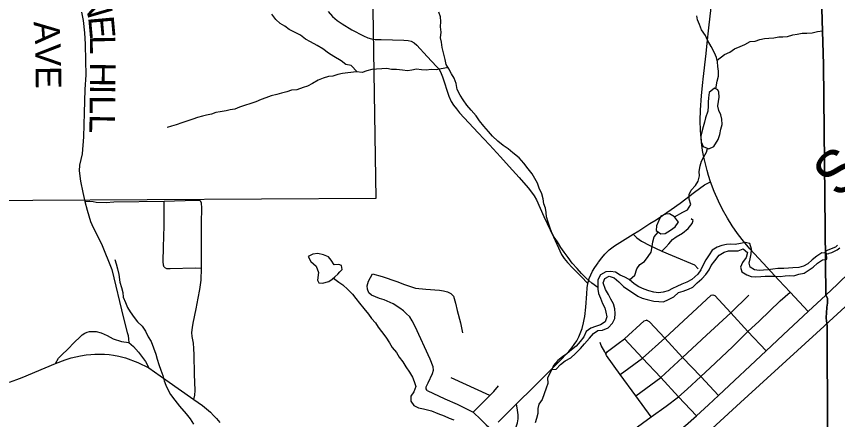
# Model space of a CAD drawing. Extents: x 0 to 34, y 0 to 22.
# Drawn here: x 4.481 to 6.308, y 17.511 to 18.409 of the extents above; entities that cross this region are included whole.
import ezdxf

# ---------------------------------------------------------------- set-up
doc = ezdxf.new("R2010")
doc.units = 0
doc.layers.add('Default', color=7, linetype='Continuous')
doc.layers.add('SH_Cut_Line', color=7, linetype='Continuous')

msp = doc.modelspace()

# ---------------------------------------------------------------- linework, layer by layer
at = {"layer": 'Default'}
for p, q in [((6.281, 17.8795), (6.2884, 17.8811)), ((5.3686, 17.8044), (5.3919, 17.8021)), ((6.2422, 17.7524), (6.282, 17.7887)), ((6.1986, 17.7113), (6.2422, 17.7524)), ((6.1986, 17.7113), (6.2422, 17.7524)), ((5.5344, 17.5651), (5.4477, 17.6045))]:
    msp.add_line(p, q, dxfattribs=at)
for points in [[(8.9, 20.9), (6.2315, 20.9), (6.2432, 19.8937), (6.2705, 18.5012), (6.2766, 18.3021), (6.2818, 17.7893), (6.284, 17.7847), (6.2852, 17.7812), (6.2857, 17.7766), (6.2851, 17.77), (6.2847, 17.7673), (6.2837, 17.7609), (6.2829, 17.749), (6.2828, 17.7387), (6.2833, 17.73), (6.2837, 17.7277), (6.2841, 17.7253), (6.2843, 17.721), (6.2843, 17.7119), (6.2861, 17.2714), (6.2871, 17.0188), (6.3215, 17.0189)], [(6.0178, 18.3496), (6.0215, 18.3835), (6.0286, 18.4495), (6.0333, 18.4968), (6.0336, 18.4999)], [(6.2861, 17.2714), (6.2843, 17.7119), (6.2843, 17.721), (6.2841, 17.7253), (6.2837, 17.7277), (6.2833, 17.73), (6.2828, 17.7387), (6.2829, 17.749), (6.2837, 17.7609), (6.2847, 17.7673), (6.2851, 17.77), (6.2857, 17.7766), (6.2852, 17.7812), (6.284, 17.7847), (6.2818, 17.7893), (6.2766, 18.3021), (6.2705, 18.5012)], [(4.6255, 18.4186), (4.6295, 18.3999), (4.6323, 18.3725), (4.6339, 18.3476), (4.6346, 18.3103), (4.6348, 18.2791), (4.6327, 18.2467), (4.631, 18.1946), (4.6296, 18.1414), (4.6272, 18.103), (4.6209, 18.0778), (4.6204, 18.0653), (4.6229, 18.0422), (4.6285, 18.0168), (4.6331, 17.9968), (4.6379, 17.9777), (4.6455, 17.9529), (4.6513, 17.9393), (4.6697, 17.903), (4.6929, 17.8458), (4.719, 17.7371), (4.7271, 17.7056), (4.7289, 17.6983), (4.7299, 17.6905), (4.7309, 17.6828)], [(5.1741, 18.42), (5.184, 18.4092), (5.1943, 18.4002), (5.2052, 18.3924), (5.227, 18.3797), (5.2531, 18.3657), (5.2625, 18.3614), (5.2706, 18.3591), (5.2792, 18.3578), (5.2906, 18.3575), (5.2926, 18.3575)], [(5.7742, 17.8052), (5.761, 17.815), (5.7487, 17.8266), (5.738, 17.8368), (5.728, 17.8477), (5.7172, 17.8598), (5.7083, 17.8726), (5.6998, 17.8839), (5.6917, 17.8949), (5.6843, 17.9073), (5.6774, 17.9179), (5.6712, 17.9296), (5.6673, 17.9398), (5.6641, 17.9508), (5.6605, 17.963), (5.6597, 17.9725), (5.6577, 17.9819), (5.6545, 17.9918), (5.6529, 18.0028), (5.6497, 18.0141), (5.6439, 18.027), (5.6403, 18.038), (5.6341, 18.0486), (5.6283, 18.0588), (5.6191, 18.0701), (5.6094, 18.0822), (5.5994, 18.0942), (5.5852, 18.1055), (5.5745, 18.1145), (5.5634, 18.1216), (5.5515, 18.1314), (5.5403, 18.1427), (5.5307, 18.1528), (5.5207, 18.1649), (5.5111, 18.177), (5.5033, 18.1875), (5.4925, 18.2007), (5.4825, 18.2117), (5.4748, 18.2234), (5.4682, 18.2339), (5.4612, 18.2468), (5.4592, 18.2597), (5.4545, 18.2714), (5.4487, 18.2816), (5.4429, 18.2926), (5.4371, 18.3024), (5.4347, 18.313), (5.4311, 18.3282), (5.4279, 18.3399), (5.4262, 18.3521), (5.4246, 18.3616), (5.4256, 18.3745), (5.424, 18.3859), (5.425, 18.3977), (5.4245, 18.4083), (5.4202, 18.4185)], [(5.2389, 18.2859), (5.2254, 18.2997), (5.2139, 18.3022), (5.2032, 18.3101), (5.1867, 18.3202), (5.1749, 18.3273), (5.1622, 18.3371), (5.15, 18.3446), (5.1351, 18.3528), (5.124, 18.3587), (5.1125, 18.3678), (5.0991, 18.3745), (5.0876, 18.3804), (5.0781, 18.3872), (5.0673, 18.3935), (5.0577, 18.4022), (5.0489, 18.4143)], [(6.0367, 18.2479), (6.0399, 18.2647), (6.0425, 18.2765), (6.0427, 18.2872), (6.0415, 18.2978), (6.041, 18.308), (6.0382, 18.3179), (6.0339, 18.3285), (6.0269, 18.3425), (6.0184, 18.3561), (6.0137, 18.3671), (6.0052, 18.3795), (6.0005, 18.3909), (5.9962, 18.4015), (5.9946, 18.4109)], [(6.04, 18.3117), (6.056, 18.3245), (6.0681, 18.33), (6.0787, 18.3369), (6.0908, 18.3419), (6.1017, 18.347), (6.1131, 18.3532), (6.1245, 18.3544), (6.1351, 18.3579), (6.1453, 18.3599), (6.1552, 18.3608), (6.1658, 18.3616), (6.1768, 18.3636), (6.1863, 18.3637), (6.1966, 18.3646), (6.2083, 18.3681), (6.2182, 18.3697), (6.2292, 18.3717), (6.2391, 18.3722), (6.2516, 18.3727), (6.263, 18.3758), (6.274, 18.3775)], [(5.2926, 18.3575), (5.343, 18.3565), (5.3521, 18.3558), (5.3592, 18.3539), (5.3657, 18.3503), (5.3716, 18.3454), (5.3949, 18.3203), (5.4155, 18.298), (5.4202, 18.2924), (5.4232, 18.2874), (5.4258, 18.2825), (5.4288, 18.2746), (5.4431, 18.2315), (5.4482, 18.2199), (5.453, 18.2118), (5.4596, 18.2033), (5.4669, 18.1943), (5.508, 18.15), (5.5334, 18.1229), (5.5581, 18.0964), (5.5772, 18.0751), (5.5991, 18.0508), (5.6191, 18.0276), (5.6271, 18.0178), (5.6328, 18.0097), (5.6379, 18.0007), (5.6543, 17.9639), (5.6755, 17.9185), (5.6829, 17.9024), (5.6938, 17.8794), (5.6997, 17.87), (5.7068, 17.8612), (5.7181, 17.8493), (5.7372, 17.8302), (5.7522, 17.8142)], [(6.009, 18.2698), (6.0153, 18.3268), (6.0178, 18.3496)], [(5.441, 18.2957), (5.4148, 18.2904), (5.4034, 18.2911), (5.392, 18.2898), (5.3817, 18.2905), (5.3707, 18.2919), (5.3604, 18.2892), (5.3509, 18.2883), (5.3395, 18.2897), (5.3262, 18.2907), (5.3152, 18.2914), (5.3049, 18.2932), (5.2939, 18.2923), (5.2817, 18.2915), (5.2715, 18.291), (5.2605, 18.2878), (5.2502, 18.2843), (5.2377, 18.2861), (5.2183, 18.2833), (5.2062, 18.2824), (5.1956, 18.2796), (5.1846, 18.2765), (5.1747, 18.2756), (5.163, 18.2714), (5.152, 18.2675), (5.1391, 18.2597), (5.1282, 18.2536), (5.1183, 18.2508), (5.1043, 18.2461), (5.0929, 18.2452), (5.082, 18.2413), (5.0702, 18.2386), (5.0604, 18.2351), (5.0475, 18.2327), (5.0354, 18.228), (5.0251, 18.2241), (5.0134, 18.2194), (5.0024, 18.2155), (4.988, 18.2108), (4.9767, 18.2069), (4.9668, 18.203), (4.9566, 18.201), (4.9471, 18.1991), (4.9342, 18.197), (4.9243, 18.195), (4.9145, 18.1919), (4.9039, 18.1892), (4.8944, 18.1872), (4.8834, 18.184), (4.8728, 18.1805), (4.8486, 18.1719), (4.8361, 18.1676), (4.8259, 18.1645), (4.8164, 18.1621), (4.816, 18.1617)], [(6.2422, 17.7524), (6.2023, 17.7949), (6.1769, 17.8221), (6.1419, 17.8597), (6.1126, 17.8917), (6.0983, 17.909), (6.0876, 17.9225), (6.0799, 17.9332), (6.0733, 17.9432), (6.0626, 17.9601), (6.0521, 17.9791), (6.0426, 17.9979), (6.0334, 18.0195), (6.0254, 18.0411), (6.0207, 18.0547), (6.0175, 18.0658), (6.0136, 18.0808), (6.0104, 18.0956), (6.0076, 18.111), (6.0051, 18.1294), (6.0028, 18.1549), (6.0019, 18.1773), (6.0026, 18.2007), (6.005, 18.233), (6.0081, 18.2618), (6.009, 18.2698)], [(6.0337, 18.2491), (6.0224, 18.2395), (6.0206, 18.2281), (6.0199, 18.2186), (6.0197, 18.2091), (6.0194, 18.1981), (6.0139, 18.1836), (6.0117, 18.174), (6.0088, 18.163), (6.0055, 18.1523), (6.0033, 18.1424), (6.0042, 18.1299), (6.0089, 18.1193), (6.0211, 18.1141), (6.0328, 18.1195), (6.0418, 18.1352), (6.0458, 18.1466), (6.048, 18.1581), (6.0509, 18.1683), (6.0504, 18.1801), (6.0484, 18.19), (6.0437, 18.1998), (6.0413, 18.2093), (6.0413, 18.21)], [(6.0413, 18.21), (6.0442, 18.2296), (6.0438, 18.2403), (6.0413, 18.2461), (6.0337, 18.2491)], [(6.282, 17.7887), (6.3073, 17.813), (6.3362, 17.8402), (6.3575, 17.8601), (6.3773, 17.8781), (6.3931, 17.8911), (6.4187, 17.9087), (6.4651, 17.9375), (6.491, 17.9548), (6.5185, 17.9718), (6.5797, 18.0093), (6.6681, 18.065), (6.6821, 18.0745), (6.7065, 18.0896), (6.7702, 18.1304)], [(5.9449, 17.963), (5.9637, 17.9734), (5.9736, 17.9788), (5.9814, 17.9903), (5.9775, 18.002), (5.9778, 18.0123), (5.9822, 18.0222), (5.9916, 18.0329), (5.9976, 18.0425), (6.0005, 18.0543), (6, 18.0641), (6.0018, 18.0763), (6.0054, 18.0866), (6.0103, 18.0969), (6.0159, 18.1072), (6.0183, 18.1153)], [(5.7762, 17.8619), (5.7832, 17.8714), (5.79, 17.8796), (5.7948, 17.8848), (5.7998, 17.8894), (5.8114, 17.898), (5.8234, 17.9056), (5.8533, 17.9243), (5.8657, 17.9321), (5.8904, 17.9478), (5.904, 17.9564), (5.9181, 17.9657), (5.9372, 17.9789), (5.9576, 17.9937), (5.9896, 18.0176), (6.0117, 18.0345), (6.0254, 18.0411)], [(4.6331, 17.9968), (4.6437, 17.9977), (4.6515, 17.997), (4.6582, 17.9956), (4.6803, 17.9948), (4.6977, 17.996), (4.8097, 17.998), (4.8792, 18.0002), (4.8851, 17.9998), (4.8885, 17.9991)], [(4.8755, 17.5559), (4.8775, 17.566), (4.878, 17.5764), (4.8766, 17.6125), (4.8758, 17.6559), (4.8757, 17.6698), (4.8745, 17.6813), (4.8719, 17.6964), (4.8713, 17.7052), (4.8724, 17.7166), (4.8742, 17.7262), (4.8809, 17.7581), (4.885, 17.7818), (4.8886, 17.8012), (4.8917, 17.8219), (4.8928, 17.8487), (4.8927, 17.8814), (4.8924, 17.9485), (4.8933, 17.9832), (4.8924, 17.9934), (4.8909, 17.9968), (4.8885, 17.9991)], [(4.8093, 17.8511), (4.8077, 17.8553), (4.8073, 17.8631), (4.8081, 17.8956), (4.8094, 17.9432), (4.8094, 17.9794), (4.8097, 17.998)], [(5.9449, 17.963), (5.9341, 17.9697), (5.9246, 17.9688), (5.9144, 17.9642), (5.9104, 17.9547), (5.9048, 17.9432), (5.9041, 17.9322), (5.9149, 17.9247), (5.9244, 17.9259), (5.9357, 17.9336), (5.9466, 17.9409), (5.953, 17.9505), (5.9537, 17.9513)], [(5.9537, 17.9513), (5.9449, 17.963)], [(6.2778, 17.7191), (6.2804, 17.7215), (6.5458, 17.9651)], [(5.9168, 17.8865), (5.9255, 17.8957), (5.9327, 17.9025), (5.9405, 17.9126), (5.9483, 17.9184), (5.9631, 17.9265), (5.9755, 17.937), (5.9841, 17.9483), (5.9865, 17.9546), (5.982, 17.9584)], [(5.8445, 17.8224), (5.8566, 17.8333), (5.861, 17.8471), (5.8681, 17.857), (5.8779, 17.8636), (5.8865, 17.8743), (5.8933, 17.8846), (5.895, 17.8971), (5.8968, 17.907), (5.8997, 17.9181), (5.9087, 17.929)], [(5.8533, 17.9243), (5.8613, 17.9164), (5.8712, 17.9089), (5.8902, 17.8992), (5.9168, 17.8865), (5.9396, 17.8768), (5.9891, 17.8558), (5.9979, 17.847)], [(6.2835, 17.8822), (6.2726, 17.8828), (6.2617, 17.8751), (6.2515, 17.8674), (6.2417, 17.8586), (6.2319, 17.8532), (6.2217, 17.8504), (6.208, 17.8492), (6.1985, 17.8487), (6.1879, 17.8478), (6.175, 17.8477), (6.1636, 17.8465), (6.1537, 17.8449), (6.1427, 17.8444), (6.1332, 17.8435), (6.1233, 17.8446), (6.113, 17.8506), (6.111, 17.86), (6.1131, 17.8696), (6.1153, 17.8802), (6.1163, 17.8909), (6.1128, 17.9034), (6.1025, 17.9055), (6.0915, 17.9039), (6.0801, 17.9012), (6.0706, 17.9018), (6.0607, 17.901), (6.0505, 17.899), (6.0399, 17.8955), (6.0289, 17.8885), (6.0218, 17.8782), (6.0147, 17.8675), (6.0095, 17.8576), (6.0036, 17.845), (5.9968, 17.8354), (5.9833, 17.8235), (5.9723, 17.8173), (5.961, 17.813), (5.9504, 17.8076), (5.9406, 17.8034), (5.9307, 17.7983), (5.9197, 17.7952), (5.9091, 17.7936), (5.8988, 17.795), (5.8878, 17.7983), (5.8771, 17.802), (5.8653, 17.8068), (5.8553, 17.814), (5.8438, 17.823), (5.8342, 17.8286), (5.8243, 17.8327), (5.814, 17.8394), (5.8029, 17.8412), (5.7919, 17.8403), (5.7806, 17.8338), (5.7746, 17.8223), (5.7743, 17.8124), (5.7741, 17.8018), (5.7757, 17.7923), (5.7804, 17.7821), (5.7847, 17.77), (5.7898, 17.7602), (5.7921, 17.7503), (5.7942, 17.7401), (5.7909, 17.729), (5.7803, 17.7225), (5.7689, 17.7189), (5.7587, 17.715), (5.7481, 17.7077), (5.7433, 17.6955), (5.7347, 17.6856), (5.7265, 17.6748), (5.7159, 17.6664), (5.7057, 17.6576), (5.6956, 17.651), (5.685, 17.6429), (5.6756, 17.6322), (5.672, 17.6233)], [(5.672, 17.6233), (5.6814, 17.6239), (5.6916, 17.6339), (5.7017, 17.6419), (5.7142, 17.6489), (5.7244, 17.6589), (5.7356, 17.6696), (5.7446, 17.6803), (5.7559, 17.693), (5.7645, 17.7029), (5.7747, 17.7095), (5.785, 17.7107), (5.7975, 17.7154), (5.8072, 17.7258), (5.8121, 17.7364), (5.8127, 17.7478), (5.8122, 17.7581), (5.809, 17.7691), (5.8036, 17.7793), (5.7978, 17.7899), (5.7912, 17.8012), (5.7865, 17.8156), (5.7898, 17.8255), (5.7996, 17.8309), (5.8107, 17.8268), (5.821, 17.8182), (5.8314, 17.808), (5.841, 17.8013), (5.8517, 17.7942), (5.8632, 17.7859), (5.8731, 17.7818), (5.8842, 17.7789), (5.8987, 17.7752), (5.9101, 17.7746), (5.9207, 17.7735), (5.9313, 17.7786), (5.9434, 17.7848), (5.9536, 17.7947), (5.9646, 17.7975), (5.9763, 17.8022), (5.9861, 17.8061), (5.9955, 17.8156), (6.0061, 17.8245), (6.0147, 17.8344), (6.0218, 17.8451), (6.0263, 17.8547), (6.0349, 17.865), (6.0446, 17.8773), (6.0556, 17.8842), (6.0654, 17.8873), (6.0863, 17.8875), (6.0977, 17.8918), (6.1073, 17.8832), (6.1047, 17.8725), (6.0965, 17.8614), (6.0921, 17.8507), (6.0948, 17.8405), (6.1059, 17.8338), (6.1159, 17.8301), (6.1261, 17.829), (6.1371, 17.8299), (6.147, 17.8307), (6.1698, 17.831), (6.1801, 17.8303), (6.1911, 17.8312), (6.2006, 17.832), (6.2105, 17.8317), (6.2219, 17.8352), (6.2332, 17.8372), (6.2536, 17.8511), (6.2634, 17.8596), (6.274, 17.8669), (6.2837, 17.8689)], [(6.3078, 17.9001), (6.3029, 17.8956), (6.2976, 17.8933), (6.2923, 17.8906), (6.2863, 17.889), (6.2798, 17.8848), (6.281, 17.8795)], [(6.2884, 17.8811), (6.2883, 17.8813), (6.2893, 17.882), (6.295, 17.8834), (6.3008, 17.8864), (6.3071, 17.8891), (6.3125, 17.8941)], [(5.2053, 17.8459), (5.2041, 17.8546), (5.198, 17.8564), (5.1877, 17.856), (5.1812, 17.8665), (5.175, 17.8741), (5.1639, 17.8785), (5.1513, 17.8811), (5.14, 17.8798), (5.1301, 17.8744), (5.1356, 17.8631), (5.1475, 17.8533), (5.153, 17.8389), (5.1505, 17.8222), (5.1532, 17.8158), (5.162, 17.8151), (5.1756, 17.8186)], [(6.2837, 17.8689), (6.2835, 17.8822)], [(4.6999, 17.8681), (4.7023, 17.8579), (4.7055, 17.8473), (4.7083, 17.8344), (4.7104, 17.8173), (4.7147, 17.8056), (4.7171, 17.7942), (4.718, 17.7843), (4.7234, 17.7722), (4.7277, 17.7609), (4.7339, 17.7511), (4.7424, 17.739), (4.7501, 17.7292), (4.7605, 17.7194), (4.7675, 17.7084), (4.7737, 17.696), (4.7803, 17.685), (4.7857, 17.6714), (4.7908, 17.6574), (4.794, 17.646), (4.7976, 17.6343), (4.8019, 17.6214), (4.8062, 17.6093), (4.8097, 17.5979), (4.8129, 17.5877), (4.818, 17.5771), (4.8238, 17.5669), (4.833, 17.5548), (4.8438, 17.5412), (4.8585, 17.5239), (4.8669, 17.5133), (4.8747, 17.5009)], [(5.7441, 17.7344), (5.7452, 17.741), (5.7475, 17.762), (5.7497, 17.7918), (5.7508, 17.8047), (5.7522, 17.8142), (5.755, 17.8253), (5.7586, 17.8341), (5.7625, 17.8417), (5.768, 17.8503), (5.7752, 17.8605), (5.7762, 17.8619)], [(4.8093, 17.8511), (4.8147, 17.8481), (4.8229, 17.8475), (4.878, 17.8496), (4.8928, 17.8487)], [(5.1756, 17.8186), (5.1833, 17.824), (5.1893, 17.8292), (5.1955, 17.8349), (5.2, 17.8406), (5.2053, 17.8459)], [(5.3944, 17.5763), (5.3924, 17.5802), (5.3927, 17.5845), (5.3966, 17.5931), (5.4065, 17.6138), (5.4085, 17.6214), (5.4082, 17.6286), (5.4009, 17.6458), (5.368, 17.7189), (5.3611, 17.731), (5.3558, 17.7399), (5.3476, 17.7478), (5.342, 17.7534), (5.3338, 17.7597), (5.3193, 17.7692), (5.2992, 17.7781), (5.2888, 17.7811), (5.2707, 17.7886), (5.2649, 17.7939), (5.2618, 17.8017), (5.2613, 17.809), (5.2638, 17.8195), (5.2727, 17.8362), (5.2948, 17.8304), (5.327, 17.8188), (5.3438, 17.8125), (5.3686, 17.8044)], [(5.1862, 17.8264), (5.1977, 17.8177), (5.2072, 17.8113), (5.218, 17.8012), (5.2284, 17.791), (5.2361, 17.7808), (5.2442, 17.7706), (5.2538, 17.7586), (5.2638, 17.7465), (5.2708, 17.7367), (5.2793, 17.7269), (5.2854, 17.7171), (5.2932, 17.7073), (5.3024, 17.6948), (5.3109, 17.682), (5.3167, 17.6722), (5.326, 17.6609), (5.3326, 17.6507), (5.3407, 17.6401), (5.3469, 17.6291), (5.355, 17.6171), (5.3623, 17.6061), (5.3659, 17.5963), (5.3694, 17.5853), (5.3646, 17.5735), (5.3586, 17.5639), (5.3584, 17.5525), (5.3649, 17.5427), (5.3753, 17.5375), (5.3867, 17.5357), (5.4046, 17.5309), (5.418, 17.5253), (5.4321, 17.5198), (5.4432, 17.5142), (5.4539, 17.5108)], [(5.3919, 17.8021), (5.422, 17.7993), (5.4307, 17.798), (5.4402, 17.7961), (5.4472, 17.7925), (5.4529, 17.7863), (5.4573, 17.7708), (5.4611, 17.7546), (5.4684, 17.7266), (5.473, 17.7049)], [(5.7174, 17.3816), (5.7506, 17.4092), (5.791, 17.4423), (5.8355, 17.4754), (5.8932, 17.5172), (5.9264, 17.5412), (5.9539, 17.5623), (5.9734, 17.579), (6.0034, 17.6071), (6.0243, 17.627), (6.0741, 17.6736), (6.1079, 17.7075), (6.1331, 17.7308), (6.1804, 17.7762), (6.2023, 17.7949)], [(5.8241, 17.6118), (5.8738, 17.6481), (5.9232, 17.6928), (6.0265, 17.7888), (6.0301, 17.7895)], [(5.859, 17.5642), (5.9143, 17.6052), (5.9629, 17.65), (6.0159, 17.6997), (6.07, 17.7491), (6.1103, 17.7885)], [(6.0301, 17.7895), (6.0348, 17.7875), (6.07, 17.7491), (6.1079, 17.7075), (6.1492, 17.6647)], [(6.2845, 17.7114), (6.2845, 17.7204), (6.2843, 17.7248), (6.2839, 17.7271), (6.2835, 17.7295), (6.283, 17.7382), (6.2831, 17.7484), (6.2839, 17.7603), (6.2849, 17.7668), (6.2853, 17.7695), (6.2859, 17.7761), (6.2854, 17.7807), (6.2842, 17.7842), (6.282, 17.7887)], [(5.5525, 17.506), (5.5932, 17.5464), (5.6317, 17.5844), (5.6742, 17.6268), (5.6939, 17.6466), (5.7025, 17.6554), (5.7096, 17.6633), (5.7166, 17.6714), (5.7218, 17.6786), (5.7273, 17.687), (5.7319, 17.6956), (5.7353, 17.7033), (5.7393, 17.7142), (5.7428, 17.727), (5.7441, 17.7344)], [(5.7925, 17.6581), (5.7956, 17.6631), (5.8198, 17.6807), (5.8338, 17.691), (5.8774, 17.7313), (5.8827, 17.7329)], [(6.0427, 17.5654), (6.0034, 17.6071), (5.9629, 17.65), (5.9232, 17.6928), (5.8891, 17.7294), (5.8827, 17.7329)], [(4.5674, 17.636), (4.5742, 17.6482), (4.5823, 17.6565), (4.5943, 17.6676), (4.6101, 17.6837), (4.6216, 17.6952), (4.6272, 17.7001), (4.6328, 17.7038), (4.6381, 17.7061), (4.6433, 17.7075), (4.6506, 17.7079), (4.6577, 17.7076), (4.669, 17.7045), (4.6824, 17.6984), (4.6958, 17.6911), (4.7143, 17.6853), (4.7309, 17.6828), (4.7414, 17.6741), (4.7523, 17.6614), (4.7682, 17.6404), (4.7751, 17.6263)], [(5.5058, 17.0111), (5.7483, 17.2351), (5.9021, 17.375), (6.092, 17.5491), (6.2778, 17.7191)], [(5.8166, 17.3768), (5.8327, 17.3899), (5.9691, 17.4982), (5.9939, 17.5197), (6.0204, 17.5442), (6.0427, 17.5654), (6.1492, 17.6647), (6.1986, 17.7113)], [(5.8166, 17.3768), (5.8327, 17.3899), (5.9691, 17.4982), (5.9939, 17.5197), (6.0204, 17.5442), (6.0427, 17.5654), (6.1492, 17.6647), (6.1986, 17.7113)], [(5.9939, 17.5197), (5.9539, 17.5623), (5.9143, 17.6052), (5.8738, 17.6481), (5.8338, 17.691)], [(5.8932, 17.5172), (5.859, 17.5642), (5.8241, 17.6118), (5.7939, 17.654), (5.7925, 17.6581), (5.7898, 17.6624), (5.7821, 17.6767), (5.7798, 17.6829)], [(4.5674, 17.636), (4.5891, 17.6445), (4.6021, 17.6486), (4.6125, 17.6514), (4.623, 17.6535), (4.6361, 17.6556), (4.646, 17.6566), (4.6553, 17.6571), (4.6668, 17.6573), (4.6764, 17.6568), (4.6868, 17.656), (4.6967, 17.6546), (4.7082, 17.6526), (4.7236, 17.6489), (4.7507, 17.6384), (4.7751, 17.6263), (4.8134, 17.5999), (4.8755, 17.5559), (4.8944, 17.5425), (4.9034, 17.5354), (4.9122, 17.5277), (4.9194, 17.5207), (4.9259, 17.5137), (4.9336, 17.5047)], [(4.4651, 17.5945), (4.4814, 17.6004), (4.4933, 17.6051), (4.5445, 17.6267), (4.5674, 17.636)], [(5.672, 17.6233), (5.6626, 17.6044), (5.6631, 17.5918), (5.6591, 17.5811), (5.6547, 17.5689), (5.6502, 17.556), (5.6431, 17.5457), (5.641, 17.5361), (5.6407, 17.5251), (5.6378, 17.5141), (5.6352, 17.5042)], [(5.4969, 17.5281), (5.5344, 17.5651), (5.5431, 17.5736), (5.5536, 17.5863)], [(5.3944, 17.5763), (5.4338, 17.5575), (5.4612, 17.546), (5.4969, 17.5281), (5.5142, 17.5118), (5.5257, 17.4999), (5.5375, 17.4893)], [(5.5314, 17.125), (5.5247, 17.1743), (5.5194, 17.2068), (5.5177, 17.235), (5.5163, 17.284), (5.5175, 17.296), (5.5203, 17.3069), (5.5299, 17.3364), (5.5414, 17.3705), (5.5608, 17.418), (5.5925, 17.4956), (5.5954, 17.5043), (5.5969, 17.5132), (5.5968, 17.5221), (5.5959, 17.532), (5.5932, 17.5464)]]:
    msp.add_lwpolyline(points, dxfattribs=at)
msp.add_lwpolyline([(4.2649, 18.9814), (5.2648, 18.9869), (5.2805, 18.0037), (4.2617, 17.9979)], close=True, dxfattribs=at)
at = {"layer": 'SH_Cut_Line'}
for points in [[(8.9, 20.9), (6.2315, 20.9), (6.2432, 19.8937), (6.2705, 18.5012), (6.2766, 18.3021), (6.2818, 17.7893), (6.284, 17.7847), (6.2852, 17.7812), (6.2857, 17.7766), (6.2851, 17.77), (6.2847, 17.7673), (6.2837, 17.7609), (6.2829, 17.749), (6.2828, 17.7387), (6.2833, 17.73), (6.2837, 17.7277), (6.2841, 17.7253), (6.2843, 17.721), (6.2843, 17.7119), (6.2861, 17.2714), (6.2871, 17.0188), (6.3215, 17.0189)], [(6.2861, 17.2714), (6.2843, 17.7119), (6.2843, 17.721), (6.2841, 17.7253), (6.2837, 17.7277), (6.2833, 17.73), (6.2828, 17.7387), (6.2829, 17.749), (6.2837, 17.7609), (6.2847, 17.7673), (6.2851, 17.77), (6.2857, 17.7766), (6.2852, 17.7812), (6.284, 17.7847), (6.2818, 17.7893), (6.2766, 18.3021), (6.2705, 18.5012)]]:
    msp.add_lwpolyline(points, dxfattribs=at)

# ---------------------------------------------------------------- texts
at = {"layer": 'Default'}
for s, height, rotation, p in [('N', 0.0568, 286.1385, (4.6268, 18.4533)), ('E', 0.0568, 275.1754, (4.6401, 18.4081)), ('A', 0.0568, 274.1126, (4.5189, 18.3973)), ('V', 0.0568, 270.9326, (4.5224, 18.3483)), ('L', 0.0568, 270.9601, (4.6439, 18.3669)), ('E', 0.0568, 270.6343, (4.5233, 18.2984)), ('H', 0.0568, 269.541, (4.6446, 18.3072)), ('Sandy', 0.09471, 44.6232, (6.3102, 18.0015)), ('I', 0.0568, 269.5004, (4.6442, 18.2573)), ('L', 0.0568, 269.4857, (4.644, 18.2339)), ('L', 0.0568, 268.7828, (4.6436, 18.1916))]:
    msp.add_text(s, height=height, rotation=rotation, dxfattribs=at).set_placement(p)

doc.saveas('drawing.dxf')
